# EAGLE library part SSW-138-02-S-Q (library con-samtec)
THROUGH-HOLE .025" SQ POST SOCKET Source: Samtec SSW.pdf
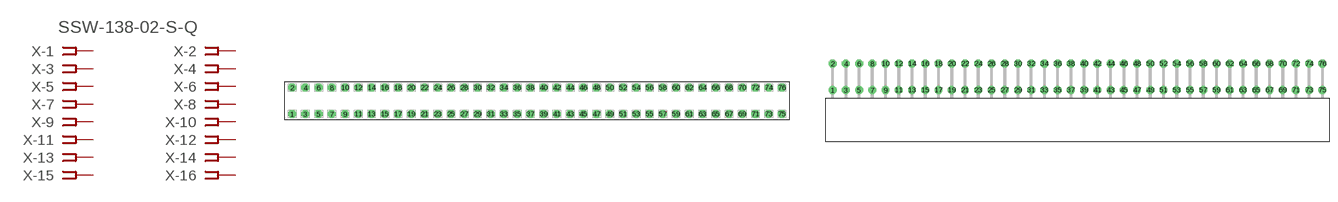
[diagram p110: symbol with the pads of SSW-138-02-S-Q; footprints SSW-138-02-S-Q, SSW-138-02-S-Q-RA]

Designator prefix X; gates -1=FPINV -2=FPIN -3=FPIN -4=FPIN -5=FPIN -6=FPIN -7=FPIN -8=FPIN -9=FPIN -10=FPIN -11=FPIN -12=FPIN -13=FPIN -14=FPIN -15=FPIN -16=FPIN -17=FPIN -18=FPIN -19=FPIN -20=FPIN -21=FPIN -22=FPIN -23=FPIN -24=FPIN -25=FPIN -26=FPIN -27=FPIN -28=FPIN -29=FPIN -30=FPIN -31=FPIN -32=FPIN -33=FPIN -34=FPIN -35=FPIN -36=FPIN -37=FPIN -38=FPIN -39=FPIN -40=FPIN -41=FPIN -42=FPIN -43=FPIN -44=FPIN -45=FPIN -46=FPIN -47=FPIN -48=FPIN -49=FPIN -50=FPIN -51=FPIN -52=FPIN -53=FPIN -54=FPIN -55=FPIN -56=FPIN -57=FPIN -58=FPIN -59=FPIN -60=FPIN -61=FPIN -62=FPIN -63=FPIN -64=FPIN -65=FPIN -66=FPIN -67=FPIN -68=FPIN -69=FPIN -70=FPIN -71=FPIN -72=FPIN -73=FPIN -74=FPIN -75=FPIN -76=FPIN

## SSW-138-02-S-Q (MPN: SSW-138-02-S-Q; OC_FARNELL: unknown; OC_NEWARK: 83P1196)  [SSW-138-02-S-Q]
1  -1:1  pas
2  -2:1  pas
3  -3:1  pas
4  -4:1  pas
5  -5:1  pas
6  -6:1  pas
7  -7:1  pas
8  -8:1  pas
9  -9:1  pas
10  -10:1  pas
11  -11:1  pas
12  -12:1  pas
13  -13:1  pas
14  -14:1  pas
15  -15:1  pas
16  -16:1  pas
17  -17:1  pas
18  -18:1  pas
19  -19:1  pas
20  -20:1  pas
21  -21:1  pas
22  -22:1  pas
23  -23:1  pas
24  -24:1  pas
25  -25:1  pas
26  -26:1  pas
27  -27:1  pas
28  -28:1  pas
29  -29:1  pas
30  -30:1  pas
31  -31:1  pas
32  -32:1  pas
33  -33:1  pas
34  -34:1  pas
35  -35:1  pas
36  -36:1  pas
37  -37:1  pas
38  -38:1  pas
39  -39:1  pas
40  -40:1  pas
41  -41:1  pas
42  -42:1  pas
43  -43:1  pas
44  -44:1  pas
45  -45:1  pas
46  -46:1  pas
47  -47:1  pas
48  -48:1  pas
49  -49:1  pas
50  -50:1  pas
51  -51:1  pas
52  -52:1  pas
53  -53:1  pas
54  -54:1  pas
55  -55:1  pas
56  -56:1  pas
57  -57:1  pas
58  -58:1  pas
59  -59:1  pas
60  -60:1  pas
61  -61:1  pas
62  -62:1  pas
63  -63:1  pas
64  -64:1  pas
65  -65:1  pas
66  -66:1  pas
67  -67:1  pas
68  -68:1  pas
69  -69:1  pas
70  -70:1  pas
71  -71:1  pas
72  -72:1  pas
73  -73:1  pas
74  -74:1  pas
75  -75:1  pas
76  -76:1  pas

## SSW-138-02-S-QRA (MPN: SSW-138-02-S-Q-RA; OC_FARNELL: unknown; OC_NEWARK: 83P1197)  [SSW-138-02-S-Q-RA]
Pads as for SSW-138-02-S-Q

## Footprint SSW-138-02-S-Q (pad centres in mm)
THROUGH-HOLE .025" SQ POST SOCKET Source: Samtec SSW.pdf
drill 1 pad 1.5 octagon: 1 -46.99,-2.54; 2 -46.99,2.54; 3 -44.45,-2.54; 4 -44.45,2.54; 5 -41.91,-2.54; 6 -41.91,2.54; 7 -39.37,-2.54; 8 -39.37,2.54; 9 -36.83,-2.54; 10 -36.83,2.54; 11 -34.29,-2.54; 12 -34.29,2.54; 13 -31.75,-2.54; 14 -31.75,2.54; 15 -29.21,-2.54; 16 -29.21,2.54; 17 -26.67,-2.54; 18 -26.67,2.54; 19 -24.13,-2.54; 20 -24.13,2.54; 21 -21.59,-2.54; 22 -21.59,2.54; 23 -19.05,-2.54; 24 -19.05,2.54; 25 -16.51,-2.54; 26 -16.51,2.54; 27 -13.97,-2.54; 28 -13.97,2.54; 29 -11.43,-2.54; 30 -11.43,2.54; 31 -8.89,-2.54; 32 -8.89,2.54; 33 -6.35,-2.54; 34 -6.35,2.54; 35 -3.81,-2.54; 36 -3.81,2.54; 37 -1.27,-2.54; 38 -1.27,2.54; 39 1.27,-2.54; 40 1.27,2.54; 41 3.81,-2.54; 42 3.81,2.54; 43 6.35,-2.54; 44 6.35,2.54; 45 8.89,-2.54; 46 8.89,2.54; 47 11.43,-2.54; 48 11.43,2.54; 49 13.97,-2.54; 50 13.97,2.54; 51 16.51,-2.54; 52 16.51,2.54; 53 19.05,-2.54; 54 19.05,2.54; 55 21.59,-2.54; 56 21.59,2.54; 57 24.13,-2.54; 58 24.13,2.54; 59 26.67,-2.54; 60 26.67,2.54; 61 29.21,-2.54; 62 29.21,2.54; 63 31.75,-2.54; 64 31.75,2.54; 65 34.29,-2.54; 66 34.29,2.54; 67 36.83,-2.54; 68 36.83,2.54; 69 39.37,-2.54; 70 39.37,2.54; 71 41.91,-2.54; 72 41.91,2.54; 73 44.45,-2.54; 74 44.45,2.54; 75 46.99,-2.54; 76 46.99,2.54

## Footprint SSW-138-02-S-Q-RA (pad centres in mm)
THROUGH-HOLE .025" SQ POST SOCKET Source: Samtec SSW.pdf
drill 1 pad 1.5 octagon: 1 -46.99,1.524; 2 -46.99,6.604; 3 -44.45,1.524; 4 -44.45,6.604; 5 -41.91,1.524; 6 -41.91,6.604; 7 -39.37,1.524; 8 -39.37,6.604; 9 -36.83,1.524; 10 -36.83,6.604; 11 -34.29,1.524; 12 -34.29,6.604; 13 -31.75,1.524; 14 -31.75,6.604; 15 -29.21,1.524; 16 -29.21,6.604; 17 -26.67,1.524; 18 -26.67,6.604; 19 -24.13,1.524; 20 -24.13,6.604; 21 -21.59,1.524; 22 -21.59,6.604; 23 -19.05,1.524; 24 -19.05,6.604; 25 -16.51,1.524; 26 -16.51,6.604; 27 -13.97,1.524; 28 -13.97,6.604; 29 -11.43,1.524; 30 -11.43,6.604; 31 -8.89,1.524; 32 -8.89,6.604; 33 -6.35,1.524; 34 -6.35,6.604; 35 -3.81,1.524; 36 -3.81,6.604; 37 -1.27,1.524; 38 -1.27,6.604; 39 1.27,1.524; 40 1.27,6.604; 41 3.81,1.524; 42 3.81,6.604; 43 6.35,1.524; 44 6.35,6.604; 45 8.89,1.524; 46 8.89,6.604; 47 11.43,1.524; 48 11.43,6.604; 49 13.97,1.524; 50 13.97,6.604; 51 16.51,1.524; 52 16.51,6.604; 53 19.05,1.524; 54 19.05,6.604; 55 21.59,1.524; 56 21.59,6.604; 57 24.13,1.524; 58 24.13,6.604; 59 26.67,1.524; 60 26.67,6.604; 61 29.21,1.524; 62 29.21,6.604; 63 31.75,1.524; 64 31.75,6.604; 65 34.29,1.524; 66 34.29,6.604; 67 36.83,1.524; 68 36.83,6.604; 69 39.37,1.524; 70 39.37,6.604; 71 41.91,1.524; 72 41.91,6.604; 73 44.45,1.524; 74 44.45,6.604; 75 46.99,1.524; 76 46.99,6.604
